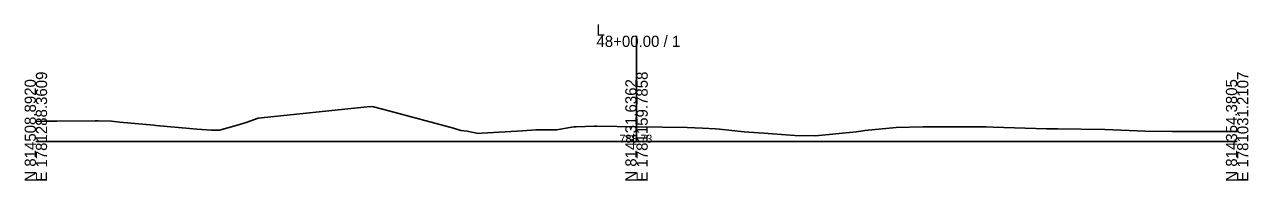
# Model space of a CAD drawing. Extents: x -26 to 7903, y -10 to 9573.
# Drawn here: x 997.2 to 1302.8, y 8990.3 to 9029.2 of the extents above; entities that cross this region are included whole.
import ezdxf

# ---------------------------------------------------------------- set-up
doc = ezdxf.new("R2010")
doc.units = 0
for name, color, linetype in [('Exist Cross Section Cell', 7, 'Continuous'), ('Exist XS Center Line Elevation Label', 7, 'Continuous'), ('Exist XS Ground Line', 7, 'Continuous')]:
    doc.layers.add(name, color=color, linetype=linetype)

msp = doc.modelspace()

# ---------------------------------------------------------------- linework, layer by layer
at = {"layer": 'Exist Cross Section Cell'}
for p, q in [((1150, 9000), (1150, 9026.44)), ((1000, 9000), (1150, 9000)), ((1150, 9000), (1300, 9000))]:
    msp.add_line(p, q, dxfattribs=at)
at = {"layer": 'Exist XS Ground Line'}
for p, q in [((1055.51, 9005.83), (1082.7, 9008.67)), ((1082.7, 9008.67), (1083.9, 9008.81)), ((1083.9, 9008.81), (1084.32, 9008.71)), ((1084.32, 9008.71), (1088.12, 9007.69)), ((1052.49, 9004.81), (1055.51, 9005.83)), ((1088.12, 9007.69), (1104.32, 9003.35)), ((1000, 9005.03), (1001.96, 9005.08)), ((1001.96, 9005.08), (1003.64, 9005.13)), ((1003.64, 9005.13), (1005.24, 9005.14)), ((1005.24, 9005.14), (1014.82, 9005.23)), ((1014.82, 9005.23), (1015.55, 9005.21)), ((1015.55, 9005.21), (1018.9, 9005.08)), ((1018.9, 9005.08), (1020.96, 9004.88)), ((1020.96, 9004.88), (1029.44, 9004.12)), ((1029.44, 9004.12), (1029.99, 9004.07)), ((1029.99, 9004.07), (1038.48, 9003.25)), ((1038.48, 9003.25), (1040.24, 9003.08)), ((1040.24, 9003.08), (1043.86, 9002.84)), ((1043.86, 9002.84), (1044.92, 9002.9)), ((1044.92, 9002.9), (1045.89, 9002.9)), ((1045.89, 9002.9), (1049.99, 9004.07)), ((1049.99, 9004.07), (1052.49, 9004.81)), ((1104.32, 9003.35), (1106.09, 9002.75)), ((1106.09, 9002.75), (1107.68, 9002.64)), ((1107.68, 9002.64), (1110.45, 9002.07)), ((1111.41, 9002.12), (1121.49, 9002.69)), ((1121.49, 9002.69), (1124.84, 9002.92)), ((1124.84, 9002.92), (1126.33, 9002.92)), ((1126.33, 9002.92), (1129.74, 9002.97)), ((1129.74, 9002.97), (1130.09, 9002.99)), ((1130.09, 9002.99), (1131.4, 9003.21)), ((1131.4, 9003.21), (1133.86, 9003.62)), ((1133.86, 9003.62), (1134.35, 9003.69)), ((1134.35, 9003.69), (1134.93, 9003.72)), ((1134.93, 9003.72), (1139.5, 9003.9)), ((1139.5, 9003.9), (1139.97, 9003.9)), ((1139.97, 9003.9), (1150.22, 9003.72)), ((1150.22, 9003.72), (1162.68, 9003.5)), ((1162.68, 9003.5), (1166.47, 9003.36)), ((1166.47, 9003.36), (1169.7, 9003.18)), ((1169.7, 9003.18), (1170.69, 9003.08)), ((1170.69, 9003.08), (1176.92, 9002.44)), ((1176.92, 9002.44), (1178.09, 9002.37)), ((1178.09, 9002.37), (1181.82, 9002.14)), ((1194.66, 9001.42), (1204.85, 9002.49)), ((1204.85, 9002.49), (1206.06, 9002.62)), ((1206.06, 9002.62), (1207.04, 9002.75)), ((1207.04, 9002.75), (1214.82, 9003.54)), ((1214.82, 9003.54), (1221.58, 9003.72)), ((1221.58, 9003.72), (1222.22, 9003.73)), ((1222.22, 9003.73), (1227.54, 9003.69)), ((1227.54, 9003.69), (1237.3, 9003.66)), ((1237.3, 9003.66), (1239.07, 9003.6)), ((1239.07, 9003.6), (1252.41, 9003.24)), ((1252.41, 9003.24), (1255.21, 9003.17)), ((1255.21, 9003.17), (1266.93, 9003.01)), ((1266.93, 9003.01), (1277.05, 9002.65)), ((1277.05, 9002.65), (1283.72, 9002.55)), ((1283.72, 9002.55), (1298.64, 9002.51)), ((1298.64, 9002.51), (1300, 9002.51)), ((1110.45, 9002.07), (1111.41, 9002.12)), ((1181.82, 9002.14), (1187.28, 9001.67)), ((1187.28, 9001.67), (1189.55, 9001.55)), ((1189.55, 9001.55), (1194.66, 9001.42))]:
    msp.add_line(p, q, dxfattribs=at)

# ---------------------------------------------------------------- texts
at = {"layer": 'Exist Cross Section Cell'}
for s, p in [('L', (1140, 9026.44)), ('48+00.00 / 1', (1140, 9023.64))]:
    msp.add_text(s, height=2.8, dxfattribs=at).set_placement(p)
for s, p in [('N 814508.8920', (1000, 8990)), ('E 1781288.3609', (1002.8, 8990)), ('N 814431.6362', (1150, 8990)), ('E 1781159.7858', (1152.8, 8990)), ('N 814354.3805', (1300, 8990)), ('E 1781031.2107', (1302.8, 8990))]:
    msp.add_text(s, height=2.8, rotation=90, dxfattribs=at).set_placement(p)
at = {"layer": 'Exist XS Center Line Elevation Label'}
msp.add_text('788.73', height=2, dxfattribs=at).set_placement((1145.75, 8999.73))

doc.saveas('drawing.dxf')
